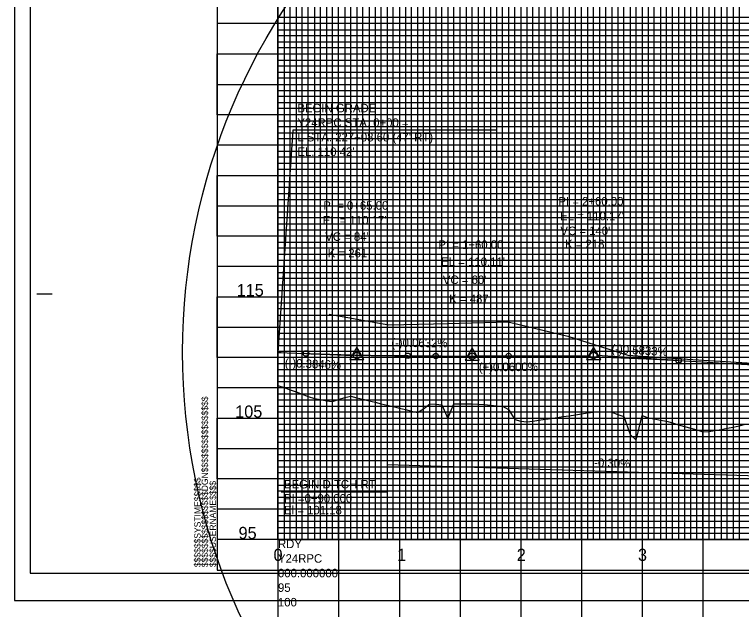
# Model space of a CAD drawing. Extents: x 2345490 to 2436403, y 465165 to 573888.
# Drawn here: x 2410678 to 2411277, y 527715 to 528205 of the extents above; entities that cross this region are included whole.
import ezdxf

# ---------------------------------------------------------------- set-up
doc = ezdxf.new("R2010")
doc.units = 0
for name, color, linetype in [('Old_Level_1', 7, 'Continuous'), ('Old_Level_18', 7, 'Continuous'), ('Old_Level_2', 7, 'Continuous'), ('Old_Level_3', 7, 'Continuous'), ('Old_Level_40', 7, 'Continuous'), ('Old_Level_41', 7, 'Continuous'), ('Old_Level_42', 7, 'Continuous'), ('Old_Level_43', 7, 'Continuous'), ('Old_Level_50', 7, 'Continuous'), ('Old_Level_51', 7, 'Continuous'), ('Old_Level_52', 7, 'Continuous'), ('Old_Level_62', 7, 'Continuous'), ('Old_Level_63', 7, 'Continuous')]:
    doc.layers.add(name, color=color, linetype=linetype)

msp = doc.modelspace()

# ---------------------------------------------------------------- linework, layer by layer
at = {"layer": 'Old_Level_1'}
msp.add_lwpolyline([(2410895.325, 527899.13175), (2410900.325, 527897.31625), (2410905.325, 527895.5035), (2410910.325, 527893.693), (2410915.325, 527891.885), (2410920.325, 527890.0795), (2410925.325, 527888.346), (2410930.325, 527887.3755), (2410935.325, 527886.411), (2410940.325, 527885.72725), (2410945.325, 527887.3925), (2410950.325, 527889.05825), (2410955.325, 527890.15175), (2410960.325, 527888.925), (2410965.325, 527887.7005), (2410970.325, 527886.47775), (2410975.325, 527885.2575), (2410980.325, 527884.03925), (2410985.325, 527882.82325), (2410990.325, 527881.60975), (2410995.325, 527880.3985), (2411000.325, 527879.18975), (2411005.325, 527877.93375), (2411010.325, 527876.6665), (2411015.325, 527879.893), (2411020.325, 527883.87575), (2411025.325, 527883.503), (2411030.325, 527883.133), (2411035.325, 527871.77675), (2411040.325, 527883.91325), (2411045.325, 527883.91925), (2411050.325, 527883.92525), (2411055.325, 527883.93125), (2411060.325, 527883.73025), (2411065.325, 527883.311), (2411070.325, 527882.85025), (2411075.325, 527882.393), (2411080.325, 527881.93875), (2411085.325, 527879.234), (2411090.325, 527871.036), (2411095.325, 527869.64375), (2411100.325, 527868.95075), (2411105.325, 527869.67875), (2411110.325, 527870.41), (2411115.325, 527871.145), (2411120.325, 527871.88325), (2411125.325, 527872.625), (2411130.325, 527873.37025), (2411135.325, 527874.119), (2411140.325, 527874.871), (2411145.325, 527875.6265), (2411150.325, 527876.38525), (2411155.325, 527877.1475), (2411160.325, 527877.43575), (2411165.325, 527877.34625), (2411170.325, 527876.95475), (2411175.325, 527875.21325), (2411180.325, 527873.416), (2411185.325, 527858.70475), (2411190.325, 527854.09575), (2411195.325, 527874.16475), (2411200.325, 527872.31375), (2411205.325, 527871.48075), (2411210.325, 527870.51025), (2411215.325, 527869.54075), (2411220.325, 527868.19025), (2411225.325, 527866.74475), (2411230.325, 527865.29575), (2411235.325, 527863.8435), (2411240.325, 527862.38775), (2411245.325, 527860.92875), (2411250.325, 527861.044), (2411255.325, 527861.95825), (2411260.325, 527862.8805), (2411265.325, 527863.81025), (2411270.325, 527864.748), (2411275.325, 527865.69375), (2411280.325, 527867.051)], dxfattribs=at)
at = {"layer": 'Old_Level_18'}
msp.add_line((2410845.325, 527747.04275), (2410845.325, 527747.04275), dxfattribs=at)
msp.add_line((2410845.325, 527747.04275), (2410845.325, 527747.04275), dxfattribs=at)
msp.add_lwpolyline([(2412345.325, 528797.04275), (2410845.325, 528797.04275), (2410845.325, 527747.04275), (2412345.325, 527747.04275)], close=True, dxfattribs=at)
at = {"layer": 'Old_Level_2'}
for p, q in [((2410907.5385, 528109.43), (2410895.325, 527926.24275)), ((2411076.005, 528109.43), (2410907.5385, 528109.43)), ((2410895.325, 527926.243), (2410918.32525, 527925.3585)), ((2410918.32525, 527925.3585), (2410957.57725, 527923.84875)), ((2411002.325, 527923.47775), (2410963.075, 527923.72575)), ((2411002.325, 527923.47775), (2411025.325, 527923.3325)), ((2411025.325, 527923.3325), (2411052.57525, 527923.1605)), ((2411085.325, 527923.323), (2411058.075, 527923.1595)), ((2411085.325, 527923.323), (2411152.57525, 527923.72675)), ((2411225.32525, 527919.65975), (2411158.0705, 527923.583)), ((2411225.32525, 527919.65975), (2411300.325, 527915.28475))]:
    msp.add_line(p, q, dxfattribs=at)
for points in [[(2410954.45375, 527920.36775), (2410966.19625, 527920.36775), (2410960.32525, 527930.4935)], [(2411049.45375, 527919.76775), (2411061.19625, 527919.76775), (2411055.32525, 527929.8935)], [(2411149.45375, 527920.36775), (2411161.19625, 527920.36775), (2411155.32525, 527930.4935)]]:
    msp.add_lwpolyline(points, close=True, dxfattribs=at)
for centre, radius in [((2410918.32525, 527925.3585), 2.25), ((2410960.325, 527923.743), 2.75), ((2411002.325, 527923.47775), 2.25), ((2411025.325, 527923.3325), 2.25), ((2411055.325, 527923.143), 2.75), ((2411085.325, 527923.323), 2.25), ((2411155.325, 527923.743), 2.75), ((2411225.32525, 527919.65975), 2.25)]:
    msp.add_circle(centre, radius, dxfattribs=at)
for points in [[(2410918.32525, 527925.3585), (2410920.00525, 527925.2945), (2410921.68525, 527925.2315), (2410923.36525, 527925.1695), (2410925.04525, 527925.10875), (2410926.72525, 527925.049), (2410928.40525, 527924.99025), (2410930.08525, 527924.93275), (2410931.76525, 527924.87625), (2410933.44525, 527924.82075), (2410935.12525, 527924.76625), (2410936.80525, 527924.713), (2410938.48525, 527924.661), (2410940.16525, 527924.60975), (2410941.84525, 527924.55975), (2410943.52525, 527924.51075), (2410945.20525, 527924.463), (2410946.88525, 527924.416), (2410948.56525, 527924.3705), (2410950.24525, 527924.32575), (2410951.92525, 527924.28225), (2410953.60525, 527924.23975), (2410955.28525, 527924.19825), (2410956.96525, 527924.158), (2410958.64525, 527924.11875), (2410960.325, 527924.08075), (2410962.005, 527924.0435), (2410963.685, 527924.0075), (2410965.365, 527923.97275), (2410967.045, 527923.93875), (2410968.725, 527923.906), (2410970.405, 527923.8745), (2410972.085, 527923.84375), (2410973.765, 527923.81425), (2410975.445, 527923.786), (2410977.125, 527923.7585), (2410978.805, 527923.73225), (2410980.485, 527923.707), (2410982.165, 527923.683), (2410983.845, 527923.66), (2410985.525, 527923.638), (2410987.205, 527923.617), (2410988.885, 527923.59725), (2410990.565, 527923.5785), (2410992.245, 527923.561), (2410993.925, 527923.5445), (2410995.605, 527923.529), (2410997.285, 527923.5145), (2410998.965, 527923.50125), (2411000.645, 527923.489), (2411002.325, 527923.47775)], [(2411025.325, 527923.3325), (2411026.525, 527923.32525), (2411027.725, 527923.318), (2411028.925, 527923.31125), (2411030.125, 527923.30475), (2411031.325, 527923.2985), (2411032.525, 527923.2925), (2411033.725, 527923.28675), (2411034.925, 527923.2815), (2411036.125, 527923.27625), (2411037.325, 527923.2715), (2411038.525, 527923.267), (2411039.725, 527923.263), (2411040.925, 527923.259), (2411042.125, 527923.2555), (2411043.325, 527923.25225), (2411044.525, 527923.24925), (2411045.725, 527923.2465), (2411046.925, 527923.244), (2411048.125, 527923.242), (2411049.325, 527923.24025), (2411050.525, 527923.2385), (2411051.725, 527923.2375), (2411052.925, 527923.2365), (2411054.125, 527923.23575), (2411055.325, 527923.2355), (2411056.525, 527923.2355), (2411057.725, 527923.23575), (2411058.925, 527923.23625), (2411060.125, 527923.237), (2411061.325, 527923.23825), (2411062.525, 527923.23975), (2411063.725, 527923.2415), (2411064.925, 527923.2435), (2411066.125, 527923.24575), (2411067.325, 527923.2485), (2411068.525, 527923.25125), (2411069.725, 527923.2545), (2411070.925, 527923.258), (2411072.125, 527923.26175), (2411073.325, 527923.266), (2411074.525, 527923.27025), (2411075.725, 527923.275), (2411076.925, 527923.28), (2411078.125, 527923.28525), (2411079.325, 527923.29075), (2411080.525, 527923.29675), (2411081.725, 527923.30275), (2411082.925, 527923.30925), (2411084.125, 527923.316), (2411085.325, 527923.323)], [(2411085.325, 527923.323), (2411088.125, 527923.338), (2411090.925, 527923.3495), (2411093.725, 527923.35725), (2411096.525, 527923.3615), (2411099.325, 527923.362), (2411102.125, 527923.359), (2411104.925, 527923.3525), (2411107.725, 527923.34225), (2411110.525, 527923.3285), (2411113.325, 527923.311), (2411116.125, 527923.29), (2411118.925, 527923.26525), (2411121.725, 527923.237), (2411124.525, 527923.20525), (2411127.325, 527923.16975), (2411130.125, 527923.13075), (2411132.925, 527923.08825), (2411135.725, 527923.042), (2411138.525, 527922.992), (2411141.325, 527922.9385), (2411144.125, 527922.8815), (2411146.925, 527922.821), (2411149.725, 527922.7565), (2411152.525, 527922.68875), (2411155.325, 527922.61725), (2411158.12525, 527922.54225), (2411160.92525, 527922.4635), (2411163.72525, 527922.38125), (2411166.52525, 527922.2955), (2411169.32525, 527922.206), (2411172.12525, 527922.11275), (2411174.92525, 527922.01625), (2411177.72525, 527921.91575), (2411180.52525, 527921.812), (2411183.32525, 527921.7045), (2411186.12525, 527921.5935), (2411188.92525, 527921.47875), (2411191.72525, 527921.3605), (2411194.52525, 527921.2385), (2411197.32525, 527921.113), (2411200.12525, 527920.984), (2411202.92525, 527920.85125), (2411205.72525, 527920.71475), (2411208.52525, 527920.575), (2411211.32525, 527920.4315), (2411214.12525, 527920.28425), (2411216.92525, 527920.1335), (2411219.72525, 527919.97925), (2411222.52525, 527919.82125), (2411225.32525, 527919.65975)]]:
    msp.add_spline(points, degree=3, dxfattribs=at)
at = {"layer": 'Old_Level_3'}
for p, q in [((2410895.325, 527772.04275), (2410895.325, 527842.4422)), ((2410895.325, 527842.4422), (2410895.325, 527600.73736)), ((2410985.325, 527833.84275), (2411407.325, 527821.24275)), ((2410985.325, 527833.84275), (2410985.32509, 527811.44435)), ((2410897.96027, 527811.44435), (2410985.32509, 527811.44435))]:
    msp.add_line(p, q, dxfattribs=at)
at = {"layer": 'Old_Level_40'}
msp.add_line((2410845.325, 527747.04275), (2410845.325, 527747.04275), dxfattribs=at)
msp.add_line((2410845.325, 527747.04275), (2410845.325, 527747.04275), dxfattribs=at)
msp.add_line((2410845.325, 527747.04275), (2410845.325, 527747.04275), dxfattribs=at)
msp.add_line((2410845.325, 527747.04275), (2410845.325, 527747.04275), dxfattribs=at)
at = {"layer": 'Old_Level_41'}
for p, q in [((2410696.825, 527974.54275), (2410709.325, 527974.54275)), ((2412345.325, 527772.04275), (2410845.325, 527772.04275))]:
    msp.add_line(p, q, dxfattribs=at)
for points in [[(2410845.325, 528797.04275), (2410895.325, 528797.04275), (2410895.325, 527772.04275), (2410945.325, 527772.04275), (2410945.325, 528797.04275), (2410995.325, 528797.04275), (2410995.325, 527772.04275), (2411045.325, 527772.04275), (2411045.325, 528797.04275), (2411095.325, 528797.04275), (2411095.325, 527772.04275), (2411145.325, 527772.04275), (2411145.325, 528797.04275), (2411195.325, 528797.04275), (2411195.325, 527772.04275), (2411245.325, 527772.04275), (2411245.325, 528797.04275), (2411295.325, 528797.04275)], [(2410920.325, 527772.04275), (2410920.325, 528797.04275), (2410970.325, 528797.04275), (2410970.325, 527772.04275), (2411020.325, 527772.04275), (2411020.325, 528797.04275), (2411070.325, 528797.04275), (2411070.325, 527772.04275), (2411120.325, 527772.04275), (2411120.325, 528797.04275), (2411170.325, 528797.04275), (2411170.325, 527772.04275), (2411220.325, 527772.04275), (2411220.325, 528797.04275), (2411270.325, 528797.04275), (2411270.325, 527772.04275), (2411320.325, 527772.04275)], [(2412345.325, 528197.04275), (2410845.325, 528197.04275), (2410845.325, 528147.04275), (2412345.325, 528147.04275)], [(2412345.325, 528122.04275), (2410845.325, 528122.04275), (2410845.325, 528172.04275), (2412345.325, 528172.04275)], [(2412345.325, 528097.04275), (2410845.325, 528097.04275), (2410845.325, 528047.04275), (2412345.325, 528047.04275)], [(2412345.325, 528022.04275), (2410845.325, 528022.04275), (2410845.325, 528072.04275), (2412345.325, 528072.04275)], [(2412345.325, 527997.04275), (2410845.325, 527997.04275), (2410845.325, 527947.04275), (2412345.325, 527947.04275)], [(2412345.325, 527897.04275), (2410845.325, 527897.04275), (2410845.325, 527847.04275), (2412345.325, 527847.04275)], [(2412345.325, 527822.04275), (2410845.325, 527822.04275), (2410845.325, 527872.04275), (2412345.325, 527872.04275)], [(2412345.325, 527797.04275), (2410845.325, 527797.04275)], [(2410882.825, 527747.04275), (2410882.825, 527747.04275)]]:
    msp.add_lwpolyline(points, dxfattribs=at)
at = {"layer": 'Old_Level_42'}
msp.add_lwpolyline([(2412345.325, 527922.04275), (2410845.325, 527922.04275), (2410845.325, 527972.04275), (2412345.325, 527972.04275)], dxfattribs=at)
at = {"layer": 'Old_Level_43'}
for points in [[(2410900.325, 528797.04275), (2410900.325, 527772.04275), (2410905.325, 527772.04275), (2410905.325, 528797.04275)], [(2410910.325, 528797.04275), (2410910.325, 527772.04275), (2410915.325, 527772.04275), (2410915.325, 528797.04275)], [(2410925.325, 528797.04275), (2410925.325, 527772.04275), (2410930.325, 527772.04275), (2410930.325, 528797.04275)], [(2410935.325, 528797.04275), (2410935.325, 527772.04275), (2410940.325, 527772.04275), (2410940.325, 528797.04275)], [(2410950.325, 528797.04275), (2410950.325, 527772.04275), (2410955.325, 527772.04275), (2410955.325, 528797.04275)], [(2410960.325, 528797.04275), (2410960.325, 527772.04275), (2410965.325, 527772.04275), (2410965.325, 528797.04275)], [(2410975.325, 528797.04275), (2410975.325, 527772.04275), (2410980.325, 527772.04275), (2410980.325, 528797.04275)], [(2410985.325, 528797.04275), (2410985.325, 527772.04275), (2410990.325, 527772.04275), (2410990.325, 528797.04275)], [(2411000.325, 528797.04275), (2411000.325, 527772.04275), (2411005.325, 527772.04275), (2411005.325, 528797.04275)], [(2411010.325, 528797.04275), (2411010.325, 527772.04275), (2411015.325, 527772.04275), (2411015.325, 528797.04275)], [(2411025.325, 528797.04275), (2411025.325, 527772.04275), (2411030.325, 527772.04275), (2411030.325, 528797.04275)], [(2411035.325, 528797.04275), (2411035.325, 527772.04275), (2411040.325, 527772.04275), (2411040.325, 528797.04275)], [(2411050.325, 528797.04275), (2411050.325, 527772.04275), (2411055.325, 527772.04275), (2411055.325, 528797.04275)], [(2411060.325, 527772.04275), (2411065.325, 527772.04275), (2411065.325, 528797.04275)], [(2411060.325, 528797.04275), (2411060.325, 527772.04275)], [(2411075.325, 528797.04275), (2411075.325, 527772.04275), (2411080.325, 527772.04275), (2411080.325, 528797.04275)], [(2411085.325, 528797.04275), (2411085.325, 527772.04275), (2411090.325, 527772.04275), (2411090.325, 528797.04275)], [(2411100.325, 528797.04275), (2411100.325, 527772.04275), (2411105.325, 527772.04275), (2411105.325, 528797.04275)], [(2411110.325, 528797.04275), (2411110.325, 527772.04275), (2411115.325, 527772.04275), (2411115.325, 528797.04275)], [(2411125.325, 528797.04275), (2411125.325, 527772.04275), (2411130.325, 527772.04275), (2411130.325, 528797.04275)], [(2411135.325, 528797.04275), (2411135.325, 527772.04275), (2411140.325, 527772.04275), (2411140.325, 528797.04275)], [(2411150.325, 528797.04275), (2411150.325, 527772.04275), (2411155.325, 527772.04275), (2411155.325, 528797.04275)], [(2411160.325, 528797.04275), (2411160.325, 527772.04275), (2411165.325, 527772.04275), (2411165.325, 528797.04275)], [(2411175.325, 528797.04275), (2411175.325, 527772.04275), (2411180.325, 527772.04275), (2411180.325, 528797.04275)], [(2411185.325, 528797.04275), (2411185.325, 527772.04275), (2411190.325, 527772.04275), (2411190.325, 528797.04275)], [(2411200.325, 528797.04275), (2411200.325, 527772.04275), (2411205.325, 527772.04275), (2411205.325, 528797.04275)], [(2411210.325, 528797.04275), (2411210.325, 527772.04275), (2411215.325, 527772.04275), (2411215.325, 528797.04275)], [(2411225.325, 528797.04275), (2411225.325, 527772.04275), (2411240.325, 527772.04275), (2411240.325, 528797.04275)], [(2411230.325, 528797.04275), (2411230.325, 527772.04275), (2411235.325, 527772.04275), (2411235.325, 528797.04275)], [(2411250.325, 528797.04275), (2411250.325, 527772.04275), (2411255.325, 527772.04275), (2411255.325, 528797.04275)], [(2411260.325, 528797.04275), (2411260.325, 527772.04275), (2411265.325, 527772.04275), (2411265.325, 528797.04275)], [(2411275.325, 528797.04275), (2411275.325, 527772.04275), (2411280.325, 527772.04275)], [(2411230.325, 528796.44275), (2411230.325, 527772.04275), (2411235.325, 527772.04275), (2411235.325, 528796.44275)], [(2412295.325, 528202.04275), (2410895.325, 528202.04275), (2410895.325, 528192.04275), (2412295.325, 528192.04275)], [(2412295.325, 528187.04275), (2410895.325, 528187.04275), (2410895.325, 528182.04275), (2412295.325, 528182.04275)], [(2412295.325, 528177.04275), (2410895.325, 528177.04275), (2410895.325, 528167.04275), (2412295.325, 528167.04275)], [(2412295.325, 528162.04275), (2410895.325, 528162.04275), (2410895.325, 528157.04275), (2412295.325, 528157.04275)], [(2412295.325, 528152.04275), (2410895.325, 528152.04275), (2410895.325, 528142.04275), (2412295.325, 528142.04275)], [(2412295.325, 528137.04275), (2410895.325, 528137.04275), (2410895.325, 528132.04275), (2412295.325, 528132.04275)], [(2412295.325, 528127.04275), (2410895.325, 528127.04275), (2410895.325, 528117.04275), (2412295.325, 528117.04275)], [(2412295.325, 528112.04275), (2410895.325, 528112.04275), (2410895.325, 528107.04275), (2412295.325, 528107.04275)], [(2412295.325, 528102.04275), (2410895.325, 528102.04275), (2410895.325, 528092.04275), (2412295.325, 528092.04275)], [(2412295.325, 528087.04275), (2410895.325, 528087.04275), (2410895.325, 528082.04275), (2412295.325, 528082.04275)], [(2412295.325, 528077.04275), (2410895.325, 528077.04275), (2410895.325, 528067.04275), (2412295.325, 528067.04275)], [(2412295.325, 528062.04275), (2410895.325, 528062.04275), (2410895.325, 528057.04275), (2412295.325, 528057.04275)], [(2412295.325, 528052.04275), (2410895.325, 528052.04275), (2410895.325, 528042.04275), (2412295.325, 528042.04275)], [(2412295.325, 528037.04275), (2410895.325, 528037.04275), (2410895.325, 528032.04275), (2412295.325, 528032.04275)], [(2412295.325, 528027.04275), (2410895.325, 528027.04275), (2410895.325, 528017.04275), (2412295.325, 528017.04275)], [(2412295.325, 528012.04275), (2410895.325, 528012.04275), (2410895.325, 528007.04275), (2412295.325, 528007.04275)], [(2412295.325, 528002.04275), (2410895.325, 528002.04275), (2410895.325, 527992.04275), (2412295.325, 527992.04275)], [(2412295.325, 527987.04275), (2410895.325, 527987.04275), (2410895.325, 527982.04275), (2412295.325, 527982.04275)], [(2412295.325, 527977.04275), (2410895.325, 527977.04275)], [(2410895.325, 527967.04275), (2412295.325, 527967.04275)], [(2412295.325, 527962.04275), (2410895.325, 527962.04275), (2410895.325, 527957.04275), (2412295.325, 527957.04275)], [(2412295.325, 527952.04275), (2410895.325, 527952.04275)], [(2410895.325, 527942.04275), (2412295.325, 527942.04275)], [(2412295.325, 527937.04275), (2410895.325, 527937.04275), (2410895.325, 527932.04275), (2412295.325, 527932.04275)], [(2412295.325, 527927.04275), (2410895.325, 527927.04275), (2410895.325, 527917.04275), (2412295.325, 527917.04275)], [(2412295.325, 527912.04275), (2410895.325, 527912.04275), (2410895.325, 527907.04275), (2412295.325, 527907.04275)], [(2412295.325, 527902.04275), (2410895.325, 527902.04275), (2410895.325, 527892.04275), (2412295.325, 527892.04275)], [(2412295.325, 527887.04275), (2410895.325, 527887.04275), (2410895.325, 527882.04275), (2412295.325, 527882.04275)], [(2412295.325, 527877.04275), (2410895.325, 527877.04275), (2410895.325, 527867.04275), (2412295.325, 527867.04275)], [(2412295.325, 527862.04275), (2410895.325, 527862.04275), (2410895.325, 527857.04275), (2412295.325, 527857.04275)], [(2412295.325, 527852.04275), (2410895.325, 527852.04275), (2410895.325, 527842.04275), (2412295.325, 527842.04275)], [(2412295.325, 527837.04275), (2410895.325, 527837.04275), (2410895.325, 527832.04275), (2412295.325, 527832.04275)], [(2412295.325, 527827.04275), (2410895.325, 527827.04275), (2410895.325, 527817.04275), (2412295.325, 527817.04275)], [(2412295.325, 527812.04275), (2410895.325, 527812.04275), (2410895.325, 527807.04275), (2412295.325, 527807.04275)], [(2412295.325, 527802.04275), (2410895.325, 527802.04275), (2410895.325, 527792.04275), (2412295.325, 527792.04275)], [(2412295.325, 527787.04275), (2410895.325, 527787.04275), (2410895.325, 527782.04275), (2412295.325, 527782.04275)], [(2412295.325, 527777.04275), (2410895.325, 527777.04275)]]:
    msp.add_lwpolyline(points, dxfattribs=at)
at = {"layer": 'Old_Level_50'}
msp.add_line((2410678.325, 527722.04275), (2410678.325, 527722.04275), dxfattribs=at)
msp.add_lwpolyline([(2412357.825, 528799.59275), (2410691.325, 528799.59275), (2410691.325, 527744.49275), (2412357.825, 527744.49275)], close=True, dxfattribs=at)
at = {"layer": 'Old_Level_51'}
msp.add_lwpolyline([(2412362.325, 528822.04275), (2410678.325, 528822.04275), (2410678.325, 527722.04275), (2412362.325, 527722.04275)], close=True, dxfattribs=at)
at = {"layer": 'Old_Level_52'}
msp.add_line((2410691.325, 527744.49275), (2410691.325, 527744.49275), dxfattribs=at)
at = {"layer": 'Old_Level_62'}
msp.add_circle((2411335.51705, 527926.51577), 518.74216, dxfattribs=at)
at = {"layer": 'Old_Level_63'}
for p, q in [((2410895.325, 527772.04275), (2410895.325, 530272.04275)), ((2411145.325, 527924.50275), (2411145.325, 528076.15275)), ((2411195.325, 527925.04275), (2411195.325, 528076.15275)), ((2411245.325, 527924.23275), (2411245.325, 528076.15275)), ((2410895.325, 527926.25275), (2410898.048, 527926.25275)), ((2410895.325, 527926.24275), (2410895.325, 527564.29475)), ((2410895.325, 527926.23275), (2410898.048, 527926.23275)), ((2410945.325, 527924.47275), (2410947.06075, 527924.47275)), ((2410945.325, 527924.46275), (2410945.325, 527564.29475)), ((2410945.325, 527924.45275), (2410947.06075, 527924.45275)), ((2410995.325, 527923.54275), (2410999.9535, 527923.54275)), ((2410995.325, 527923.53275), (2410995.325, 527564.29475)), ((2410995.325, 527923.52275), (2410999.9535, 527923.52275)), ((2411045.325, 527923.25275), (2411047.927, 527923.25275)), ((2411045.325, 527923.24275), (2411045.325, 527564.29475)), ((2411045.325, 527923.23275), (2411047.927, 527923.23275)), ((2411095.325, 527923.36275), (2411095.331, 527923.36275)), ((2411095.325, 527923.35275), (2411095.325, 527564.29475)), ((2411095.325, 527923.34275), (2411095.331, 527923.34275)), ((2411145.325, 527922.52275), (2411145.325, 527564.29475)), ((2411195.325, 527919.28275), (2411195.325, 527564.29475)), ((2411245.325, 527913.62275), (2411245.325, 527564.29475)), ((2410895.325, 527772.04275), (2413081.64925, 527772.04275)), ((2410895.325, 527772.04275), (2410895.325, 525272.04275))]:
    msp.add_line(p, q, dxfattribs=at)
msp.add_lwpolyline([(2410937.46001, 527957.6808), (2410986.64001, 527948.9808), (2411035.83001, 527950.0808), (2411085.01001, 527951.5808), (2411134.21001, 527939.5808), (2411183.43001, 527923.9808), (2411232.67001, 527920.7808), (2411281.95001, 527917.6808), (2411331.27001, 527914.4808), (2411380.65001, 527911.1808), (2411426.73001, 527909.8808), (2411471.73001, 527905.9808), (2411521.73001, 527907.3808), (2411571.73001, 527908.8808), (2411616.73001, 527910.2808), (2411666.73001, 527911.7808), (2411716.73001, 527939.3808), (2411746.73001, 527928.4808), (2411796.73001, 527927.4808), (2411846.73001, 527909.0808)], dxfattribs=at)

# ---------------------------------------------------------------- texts
at = {"layer": 'Old_Level_2'}
for s, height, p in [('BEGIN GRADE', 7.0000005, (2410911.29775, 528124.0405)), ('Y24RPC STA. 0+00 =', 7.0000005, (2410911.29775, 528112.0405)), ("L STA. 227+08.60 (47' RT)", 7.0000005, (2410911.29775, 528100.0405)), ("EL. 110.42'", 7.0000005, (2410911.29775, 528088.0405)), ('PI = 0+65.00', 7.0000005, (2410932.625, 528043.77875)), ('PI = 2+60.00', 7.0000005, (2411126.325, 528047.243)), ("EL = 110.17'", 7.0000005, (2410932.165, 528031.6005)), ("EL = 110.17'", 7.0000005, (2411127.705, 528035.065)), ("VC = 84'", 7.000001, (2410934.21675, 528018.156)), ("VC = 140'", 7.000001, (2411127.9535, 528022.89475)), ('PI = 1+60.00', 7.0000005, (2411027.44825, 528011.5675)), ('K = 218', 7.000001, (2411131.7435, 528012.0395)), ('K = 261', 7.000001, (2410936.3225, 528004.56275)), ("EL = 110.11'", 7.0000005, (2411029.76425, 527997.43225)), ("VC = 60'", 7.000001, (2411031.11175, 527982.59025)), ('K = 487', 7.000001, (2411036.3755, 527966.89075))]:
    msp.add_text(s, height=height, dxfattribs=at).set_placement(p)
for s, rotation, p in [('(-)0.0632%', 359.63813611, (2410988.63075, 527930.75925)), ('(-)0.5833%', 356.66153056, (2411169.851, 527925.901)), ('(-)0.3846%', 357.79740278, (2410900.874, 527914.19575)), ('(+)0.0600%', 0.34376944, (2411060.7785, 527910.667))]:
    msp.add_text(s, height=7.000001, rotation=rotation, dxfattribs=at).set_placement(p)
at = {"layer": 'Old_Level_3'}
for s, height, rotation, p in [('-0.30%', 7.000001, 358.28978066, (2411155.73571, 527832.04891)), ('BEGIN DITCH RT', 7.0000005, 360, (2410900.3286, 527814.24203)), ('PI =0+90.000', 7.0000005, 360, (2410900.3286, 527802.54268)), ('El = 101.18', 7.0000005, 360, (2410900.3286, 527792.87215))]:
    msp.add_text(s, height=height, rotation=rotation, dxfattribs=at).set_placement(p)
at = {"layer": 'Old_Level_41'}
for s, p in [('$$$$$$$$$$$$$$$$DGN$$$$$$$$$$$$$$$$', (2410837.675, 527749.40525)), ('$$$$$$SYSTIME$$$$$', (2410831.625, 527749.40525)), ('$$$$USERNAME$$$$', (2410844.25, 527749.41775))]:
    msp.add_text(s, height=5.25, rotation=90, dxfattribs=at).set_placement(p)
at = {"layer": 'Old_Level_62'}
for s, height, p in [('115', 10.000001, (2410861.3085, 527972.543)), ('105', 10.000001, (2410860.1115, 527872.543)), ('95', 10.000001, (2410862.869, 527772.543)), ('0', 10, (2410891.666, 527754.543)), ('1', 10, (2410993.5055, 527754.543)), ('2', 10, (2411092.054, 527754.543)), ('3', 10, (2411191.88875, 527754.543))]:
    msp.add_text(s, height=height, dxfattribs=at).set_placement(p)
at = {"layer": 'Old_Level_63'}
for s, p in [('RDY', (2410895.325, 527765.04275)), ('Y24RPC', (2410895.325, 527753.04275)), ('000.000000', (2410895.325, 527741.04275)), ('95', (2410895.325, 527729.04275)), ('100', (2410895.325, 527717.04275))]:
    msp.add_text(s, height=7.000001, dxfattribs=at).set_placement(p)

doc.saveas('drawing.dxf')
